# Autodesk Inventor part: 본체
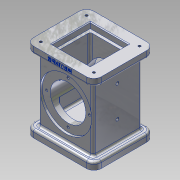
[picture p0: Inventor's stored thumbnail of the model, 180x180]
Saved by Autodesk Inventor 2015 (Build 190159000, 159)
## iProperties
Created: 2017-08
Part Number: 본체
Material: 알루미늄 6061
Document SubType Name: Modeling
Designer: Administrator
Mass: 869.109 g
Surface Area: 642.254 cm^2
Volume: 321.892 cm^3
Density: 2.7 g/cm^3
Appearance: 알루미늄 - 평지
Author: Administrator
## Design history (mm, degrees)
sketch "스케치1"
  geometry: L1 (41, 46)-(-41, 46); L2 (-41, 46)-(-41, -46); L3 (-41, -46)-(41, -46); L4 (41, -46)-(41, 46); 3 further points
  constraints: 8 end point, 2 midpoint, 2 parallel, 1 horizontal, 1 horizontal alignment, 1 perpendicular, 1 vertical alignment
  dimensions: "d0" = 92 distance of L3.end L1.start; "d1" = 82 distance of L2.end L3.end
extrude "돌출1" new body sketch "스케치1" distance "d2" = 108; taper "d3" = 0 deg
node "작업 평면1"
sketch "스케치2"
  geometry: L1 (33, 37)-(-33, 37); L2 (-33, 37)-(-33, -37); L3 (-33, -37)-(33, -37); L4 (33, -37)-(33, 37); L5 (58.021, 66.542)-(-62.586, 66.542); L6 (-62.586, 66.542)-(-62.586, -75.451); L7 (-62.586, -75.451)-(58.021, -75.451); L8 (58.021, -75.451)-(58.021, 66.542); 3 further points
  constraints: 16 end point, 4 parallel, 2 horizontal, 2 midpoint, 2 perpendicular, 1 horizontal alignment, 1 vertical alignment
  dimensions: "d5" = 74 distance of L3.end L1.start; "d6" = 66 distance of L2.end L3.end
extrude "돌출2" cut sketch "스케치2" distance "d7" = 88; taper "d8" = 0 deg
sketch "스케치3"
  geometry: L1 (-33, 10)-(-33, 98) reference; L2 (-33, 89)-(-30, 89); L3 (-30, 89)-(-30, 54); L4 (-30, 54)-(-33, 54); L5 (-33, 54)-(-33, 89); L6 (-30, 54)-(30, 54); L7 (30, 54)-(30, 78); L8 (30, 78)-(-30, 78); L9 (-30, 78)-(-30, 54); L10 (33, 10)-(33, 98) reference; L11 (30, 54)-(33, 54); L12 (33, 54)-(33, 89); L13 (33, 89)-(30, 89); L14 (30, 89)-(30, 54); L15 (-41, 0)-(41, 0) reference; L16 (41, 108)-(-41, 108) reference; L17 (-26, 108)-(26, 108); L18 (26, 108)-(26, 100); L19 (26, 100)-(-26, 100); L20 (-26, 100)-(-26, 108); L21 (41, 0)-(-41, 0) reference; L22 (-24, 0)-(24, 0); L23 (24, 0)-(24, 16); L24 (24, 16)-(-24, 16); L25 (-24, 16)-(-24, 0); L26 (-22, 100)-(22, 100); L27 (22, 100)-(22, 26); L28 (22, 26)-(-22, 26); L29 (-22, 26)-(-22, 100); 7 further points
  constraints: 48 end point, 12 parallel, 6 horizontal, 6 midpoint, 6 perpendicular, 5 point on line, 2 vertical alignment, 1 coincident
  dimensions: "d9" = 54 distance from line of L15 L4.end; "d10" = 70 diameter of L2 L6; "d11" = 70 diameter of L13 L11; "d12" = 48 diameter of L8 L6; "d13" = 3 distance of L2.start L2.end; "d14" = 3 distance of L12.end L13.end; "d15" = 52 distance of L17.start L17.end; "d16" = 8 distance of L17.end L18.end; "d17" = 16 distance of L22.end L23.end; "d18" = 48 distance of L22.start L22.end; "d19" = 44 distance of L27.end L28.end; "d20" = 74 distance of L28.end L26.start
extrude "돌출3" cut sketch "스케치3" stored distance "d21" = 52; taper "d22" = 0 deg
extrude "돌출4" cut sketch "스케치3" stored distance "d23" = 44; taper "d24" = 0 deg
revolve "회전1" stored, may be unused: angle "d25" = 90 deg
extrude "돌출5" cut sketch "스케치3" stored distance "d26" = 48; taper "d27" = 0 deg
sketch "스케치4" dims "d28" = 58
  geometry: 3 further points
  constraints: 1 vertical alignment, 2 other
hole "구멍1" sketch "스케치4" at (0, 29) diameter "d29" = 3.242; stored, may be unused: countersink angle "d33" = 90 deg, drill point angle "d35" = 118 deg; dims "d30" = 4, "d31" = 4, "d32" = 2, "d34" = 6
sketch "스케치5"
  geometry: L1 (33, -10)-(33, 28); L2 (33, 28)-(33, 70); L3 (0, 0)-(0, 88) reference; 2 further points
  constraints: 4 end point, 2 coincident, 1 point on line, 1 vertical
  dimensions: "d39" = 38 distance of L1.start L1.end; "d40" = 42 distance of L1.end L2.end; "d41" = 33 distance between parallel lines of L3 L2 (derived)
hole "구멍2" sketch "스케치5" at (33, 28), (33, 70) diameter "d42" = 4.134; stored, may be unused: countersink angle "d46" = 90 deg, drill point angle "d48" = 118 deg; dims "d43" = 10, "d44" = 4, "d45" = 2, "d47" = 20
sketch "스케치6"
  geometry: L1 (0, 0)-(92, 0) reference; L2 (0, -10)-(0, 0) reference; 2 further points
  constraints: 1 other
  dimensions: "d49" = 4 distance from line of L1 point (46, -4); "d50" = 46 distance from line of L2 point (46, -4)
fillet "모깎기1" dims "d51" = 10
fillet "모깎기2" dims "d52" = 3
chamfer "모따기1" distance "d53" = 1; stored, may be unused: second distance "d54" = 2, angle "d55" = 45 deg
feature "엠보싱1" dims "d0" = 92, "d1" = 82, "d56" = 0.5, "d57" = 0
fillet "모깎기3" dims "d58" = 3
sketch "스케치7"
  geometry: A1 r 10 centre (31, 36) between (41, 36) and (31, 46) reference; 2 further points
  constraints: 1 coincident
hole "구멍3" sketch "스케치7" at (31, 36) diameter "d59" = 3.242; stored, may be unused: countersink angle "d63" = 90 deg, drill point angle "d65" = 118 deg; dims "d60" = 4, "d61" = 4, "d62" = 2, "d64" = 6
sketch "스케치8"
  geometry: A1 r 10 centre (-31, -36) between (-41, -36) and (-31, -46) reference; 2 further points
  constraints: 1 coincident
hole "구멍4" sketch "스케치8" at (-31, -36) diameter "d66" = 3.242; stored, may be unused: countersink angle "d70" = 90 deg, drill point angle "d72" = 118 deg; dims "d67" = 4, "d68" = 4, "d69" = 2, "d71" = 6
fillet "모깎기4" dims "d73" = 3
node "솔리드1"
pattern_circular "원형 패턴1" dims angle "d37" = 360 deg
mirror "대칭1"
mirror "대칭2"
mirror "대칭3"
mirror "대칭4"
mirror "대칭5"
